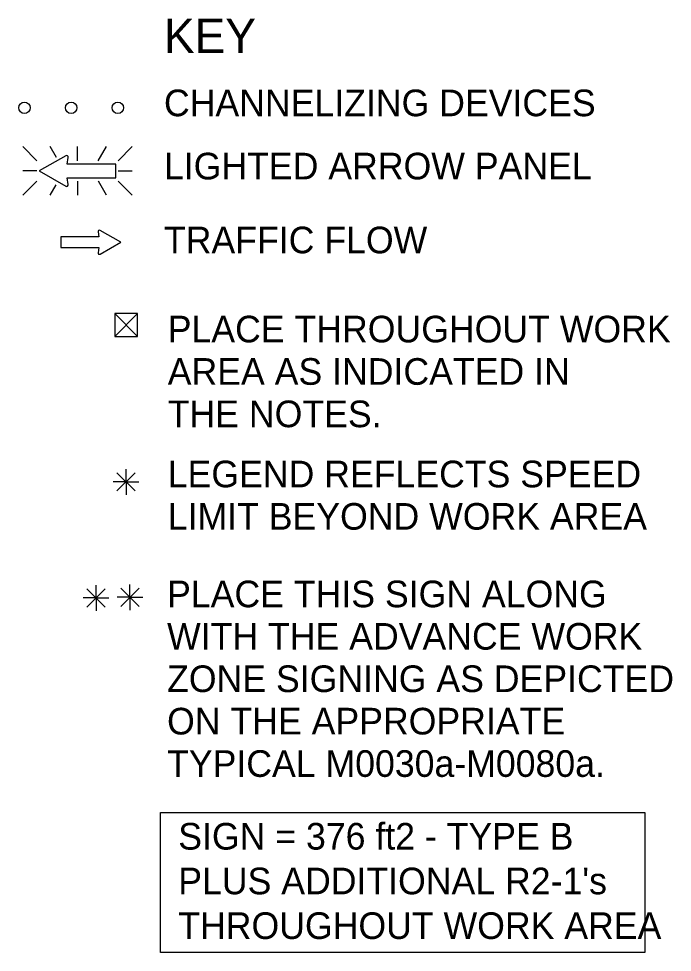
# Model space of a CAD drawing. Extents: x 16553 to 18478, y 5759 to 7026.
# Drawn here: x 17180.9 to 17409, y 6598.5 to 6924.4 of the extents above; entities that cross this region are included whole.
import ezdxf

# ---------------------------------------------------------------- set-up
doc = ezdxf.new("R2010")
doc.units = 0
for name, color, linetype in [('MT_SCRATCH_LEVEL_E', 7, 'Continuous'), ('TRAFFIC_SIGNS_PR', 7, 'Continuous'), ('TYPICAL_TEXT_DIMEN_EX', 7, 'Continuous'), ('TYPICAL_TEXT_DIMEN_PR', 7, 'Continuous')]:
    doc.layers.add(name, color=color, linetype=linetype)

msp = doc.modelspace()

# ---------------------------------------------------------------- linework, layer by layer
at = {"layer": 'MT_SCRATCH_LEVEL_E'}
for p, q in [((17208.65, 6849.99), (17208.96, 6848.21)), ((17216.57, 6846.36), (17209.33, 6850.47)), ((17208.96, 6848.21), (17195.71, 6848.21)), ((17195.71, 6848.21), (17195.71, 6844.47)), ((17195.71, 6844.47), (17208.96, 6844.47)), ((17208.96, 6844.47), (17208.65, 6842.69)), ((17209.33, 6842.22), (17216.57, 6846.36))]:
    msp.add_line(p, q, dxfattribs=at)
for centre, start, end in [((17209.11, 6850.07), 60.4248, 189.9638), ((17209.11, 6842.62), 170.0362, 299.7731)]:
    msp.add_arc(centre, 0.463, start, end, dxfattribs=at)
at = {"layer": 'TRAFFIC_SIGNS_PR'}
for p, q in [((17182.39, 6879.74), (17187.32, 6874.81)), ((17194.15, 6875.92), (17191.94, 6879.75)), ((17201.47, 6874.81), (17201.47, 6879.75)), ((17208.7, 6874.81), (17211.55, 6879.75)), ((17215.62, 6874.81), (17220.55, 6879.75)), ((17187.32, 6871.26), (17182.39, 6871.26)), ((17215.62, 6871.26), (17220.55, 6871.26)), ((17182.39, 6862.77), (17187.32, 6867.7)), ((17191.9, 6862.77), (17194.01, 6866.43)), ((17201.47, 6867.7), (17201.47, 6862.77)), ((17211.6, 6862.77), (17208.75, 6867.7)), ((17215.62, 6867.7), (17220.55, 6862.76))]:
    msp.add_line(p, q, dxfattribs=at)
for points in [[(17197.4, 6876.53), (17188.1, 6871.26), (17197.4, 6865.94)], [(17198.27, 6866.56), (17197.87, 6868.83), (17214.88, 6868.83), (17214.88, 6873.63), (17197.87, 6873.63), (17198.27, 6875.91)]]:
    msp.add_lwpolyline(points, dxfattribs=at)
for centre in [(17182.95, 6893.29), (17199.25, 6893.29), (17215.55, 6893.29)]:
    msp.add_circle(centre, 2, dxfattribs=at)
for centre, radius, start, end in [((17197.68, 6876.01), 0.598, 350.7308, 118.8916), ((17197.68, 6866.46), 0.597, 241.4833, 9.9593)]:
    msp.add_arc(centre, radius, start, end, dxfattribs=at)
at = {"layer": 'TYPICAL_TEXT_DIMEN_EX'}
msp.add_lwpolyline([(17230.4, 6647.34), (17399.41, 6647.34), (17399.41, 6598.51), (17230.4, 6598.51)], close=True, dxfattribs=at)
at = {"layer": 'TYPICAL_TEXT_DIMEN_PR'}
for p, q in [((17214.46, 6821.48), (17222.46, 6813.48)), ((17214.46, 6813.48), (17222.46, 6821.48)), ((17221.61, 6765.91), (17215.23, 6759.54)), ((17215.24, 6765.91), (17221.61, 6759.54)), ((17218.42, 6762.73), (17218.42, 6767.18)), ((17218.42, 6762.73), (17213.89, 6762.73)), ((17218.42, 6762.73), (17221.61, 6762.73)), ((17218.42, 6762.73), (17222.9, 6762.73)), ((17218.42, 6762.73), (17218.42, 6758.23)), ((17207.95, 6722.19), (17207.95, 6726.64)), ((17219.79, 6722.45), (17219.79, 6726.91)), ((17204.77, 6725.37), (17211.14, 6719)), ((17211.14, 6725.37), (17204.77, 6719)), ((17216.6, 6725.64), (17222.98, 6719.26)), ((17222.98, 6725.64), (17216.6, 6719.26)), ((17207.95, 6722.19), (17203.42, 6722.19)), ((17207.95, 6722.19), (17211.14, 6722.19)), ((17207.95, 6722.19), (17212.43, 6722.19)), ((17207.95, 6722.19), (17207.95, 6717.69)), ((17219.79, 6722.45), (17215.26, 6722.45)), ((17219.79, 6722.45), (17222.98, 6722.45)), ((17219.79, 6722.45), (17224.27, 6722.45)), ((17219.79, 6722.45), (17219.79, 6717.95))]:
    msp.add_line(p, q, dxfattribs=at)
msp.add_lwpolyline([(17214.46, 6821.48), (17214.46, 6813.48), (17222.46, 6813.48), (17222.46, 6821.48)], close=True, dxfattribs=at)
msp.add_open_spline([(17311.37, 6763.31), (17311.39, 6763.31), (17311.4, 6763.31), (17311.4, 6763.31)], degree=2, dxfattribs=at)

# ---------------------------------------------------------------- texts
at = {"layer": 'TYPICAL_TEXT_DIMEN_EX'}
for s, height, p in [('KEY', 12, (17231.64, 6912.39)), ('CHANNELIZING DEVICES', 9.3, (17231.64, 6890.34)), ('LIGHTED ARROW PANEL', 9.3, (17231.64, 6868.29)), ('TRAFFIC FLOW', 9.3, (17231.64, 6842.49)), ('PLACE THROUGHOUT WORK', 9.3, (17232.96, 6811.4)), ('AREA AS INDICATED IN', 9.3, (17232.96, 6796.6)), ('THE NOTES.', 9.3, (17232.96, 6781.8)), ('LEGEND REFLECTS SPEED', 9.3, (17232.97, 6760.82)), ('LIMIT BEYOND WORK AREA', 9.3, (17232.97, 6746.03)), ('PLACE THIS SIGN ALONG', 9.3, (17232.73, 6718.95)), ('WITH THE ADVANCE WORK', 9.3, (17232.73, 6704.15)), ('ZONE SIGNING AS DEPICTED', 9.3, (17232.73, 6689.35)), ('ON THE APPROPRIATE', 9.3, (17232.73, 6674.55)), ('TYPICAL M0030a-M0080a.', 9.3, (17232.73, 6659.75)), ('SIGN = 376 ft2 - TYPE B', 9.3, (17236.63, 6634.37)), ("PLUS ADDITIONAL R2-1's", 9.3, (17236.63, 6618.77)), ('THROUGHOUT WORK AREA', 9.3, (17236.63, 6603.17))]:
    msp.add_text(s, height=height, dxfattribs=at).set_placement(p)

doc.saveas('drawing.dxf')
